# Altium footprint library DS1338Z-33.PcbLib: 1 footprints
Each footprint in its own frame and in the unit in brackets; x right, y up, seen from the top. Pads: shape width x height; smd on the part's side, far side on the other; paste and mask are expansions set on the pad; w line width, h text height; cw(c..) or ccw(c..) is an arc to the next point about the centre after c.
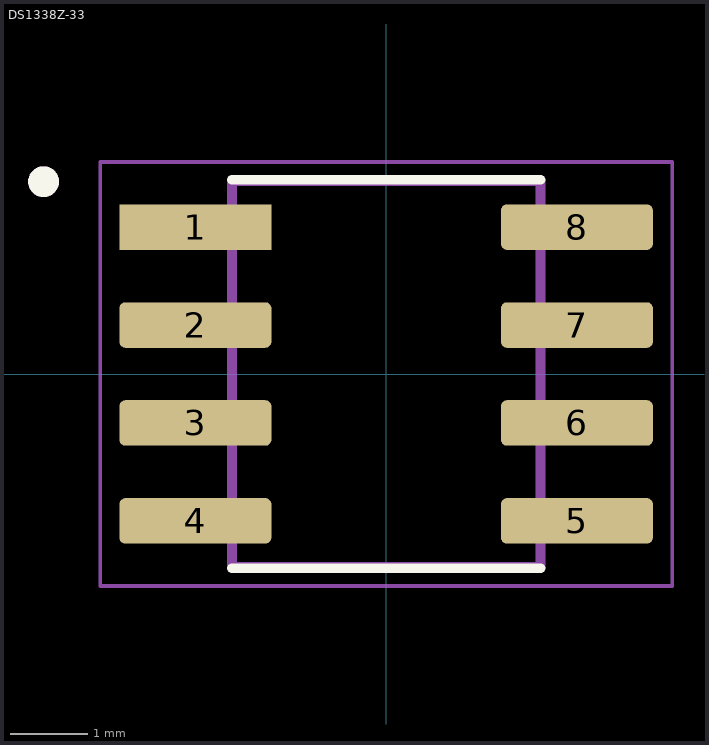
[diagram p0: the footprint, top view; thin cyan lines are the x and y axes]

## DS1338Z-33 [mm]
pads (8):
  rect 1.97x0.59 smd: 1(-2.475,1.905)
  rrect25% 1.97x0.59 smd: 2(-2.475,0.635) 3(-2.475,-0.635) 4(-2.475,-1.905) 5(2.475,-1.905) 6(2.475,-0.635) 7(2.475,0.635) 8(2.475,1.905)
Top Overlay:
  circle w0.2: c-4.445,2.495 r0.1
  lines w0.127: -2,-2.52 2,-2.52 ; -2,2.52 2,2.52
Mechanical 13:
  circle w0.2: c-4.445,2.495 r0.1
  lines w0.127: -2,-2.5 2,-2.5 2,2.5 -2,2.5 -2,-2.5
Mechanical 15:
  lines w0.05: -3.71,-2.75 3.71,-2.75 3.71,2.75 -3.71,2.75 -3.71,-2.75
3D body "DS1338Z-33.STEP": height 1.75, standoff 0, extent -2.975,-2.465 3.024,2.435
